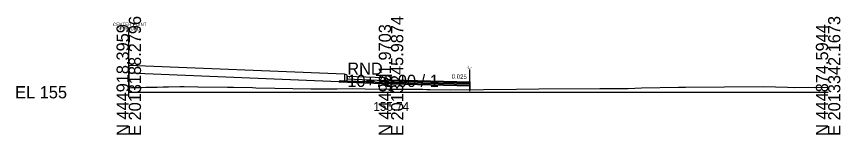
# Model space of a CAD drawing. Extents: x -26 to 163, y -10 to 7518.
# Drawn here: x -25.7 to 162.8, y 1490.3 to 1517.4 of the extents above; entities that cross this region are included whole.
import ezdxf

# ---------------------------------------------------------------- set-up
doc = ezdxf.new("R2010")
doc.units = 0
for name, color, linetype in [('Exist Cross Section Cell', 7, 'Continuous'), ('Exist XS Center Line Elevation Label', 7, 'Continuous'), ('Exist XS Ground Line', 7, 'Continuous'), ('Prop CMT Conc Surface', 7, 'Continuous'), ('Prop CMT Concrete Structures', 7, 'Continuous'), ('Prop CMT Pvmt Course 1', 7, 'Continuous'), ('Prop CMT Pvmt Course 1 CG', 7, 'Continuous'), ('Prop CMT Pvmt Course 2', 7, 'Continuous'), ('Prop CMT Pvmt Course 3', 7, 'Continuous'), ('Prop CMT Pvmt Surface', 7, 'Continuous'), ('Prop CMT Shear Line', 7, 'Continuous'), ('Prop CMT Shear Line Text', 7, 'Continuous'), ('Prop CMT Slope Grass', 7, 'Continuous'), ('Prop CMT Subgrade Earthwork', 7, 'Continuous'), ('Prop XS Earthwork Shape', 7, 'Continuous'), ('Prop XS SE Text', 7, 'Continuous')]:
    doc.layers.add(name, color=color, linetype=linetype)

msp = doc.modelspace()

# ---------------------------------------------------------------- linework, layer by layer
at = {"layer": 'Exist Cross Section Cell'}
for p, q in [((60, 1500), (60, 1504.01)), ((0, 1500), (60, 1500)), ((60, 1500), (160, 1500))]:
    msp.add_line(p, q, dxfattribs=at)
at = {"layer": 'Exist XS Ground Line'}
msp.add_lwpolyline([(0, 1501.05), (0.62, 1501.07), (1.28, 1501.08), (2.96, 1501.11), (3.88, 1501.13), (4.24, 1501.14), (6.47, 1501.19), (7.87, 1501.22), (9.06, 1501.24), (11.68, 1501.3), (12.09, 1501.31), (12.69, 1501.31), (15.79, 1501.24), (22.57, 1501.13), (23.98, 1501.14), (28.29, 1501.07), (29.1, 1501.05), (33.4, 1500.92), (41.68, 1500.81), (46.12, 1500.76), (47.66, 1500.75), (51.09, 1500.83), (54.12, 1500.79), (60, 1500.74), (67.25, 1500.68), (68.23, 1500.67), (68.95, 1500.66), (73.61, 1500.59), (88.71, 1500.68), (93.79, 1500.76), (107.77, 1500.83), (114.24, 1500.87), (117.29, 1501), (125.76, 1501.18), (126.54, 1501.19), (127.38, 1501.2), (145.24, 1501.34), (150.72, 1501.14), (152.39, 1501.11), (157.08, 1501.14), (160, 1501.1)], dxfattribs=at)
at = {"layer": 'Prop CMT Conc Surface'}
for points in [[(50, 1503.82), (49.96, 1503.92), (49.85, 1503.96), (49.34, 1504.15)], [(50, 1503.65), (50, 1503.82)], [(60, 1502.85), (59.25, 1502.87), (59.25, 1503.04), (58.5, 1503.29)]]:
    msp.add_lwpolyline(points, dxfattribs=at)
at = {"layer": 'Prop CMT Concrete Structures'}
for points in [[(50, 1503.82), (49.96, 1503.92), (49.85, 1503.96), (49.34, 1504.15)], [(49.34, 1504.15), (49.34, 1502.65)], [(49.34, 1502.65), (50, 1502.65)], [(50, 1503.65), (50, 1503.82)], [(50, 1502.65), (50, 1503.65)], [(50, 1503.65), (50, 1503.07)], [(58.5, 1503.29), (50, 1503.63)], [(50, 1503.05), (58.5, 1502.71)], [(60, 1502.85), (59.25, 1502.87), (59.25, 1503.04), (58.5, 1503.29)], [(58.5, 1503.29), (58.5, 1502.31)], [(58.5, 1502.71), (58.5, 1503.29)], [(60, 1502.27), (60, 1502.85)], [(58.5, 1502.31), (60, 1502.27)]]:
    msp.add_lwpolyline(points, dxfattribs=at)
at = {"layer": 'Prop CMT Pvmt Course 1'}
for points in [[(60, 1502.85), (78, 1502.4)], [(60, 1502.6), (60, 1502.85)], [(78, 1502.15), (60, 1502.6)], [(78, 1502.4), (78, 1502.15)]]:
    msp.add_lwpolyline(points, dxfattribs=at)
msp.add_lwpolyline([(60, 1502.6), (60, 1502.73), (60, 1502.73), (60, 1502.6)], close=True, dxfattribs=at)
at = {"layer": 'Prop CMT Pvmt Course 1 CG'}
for points in [[(60, 1501.94), (60, 1502.27)], [(78, 1501.49), (78, 1501.82)]]:
    msp.add_lwpolyline(points, dxfattribs=at)
at = {"layer": 'Prop CMT Pvmt Course 2'}
for points in [[(60, 1502.27), (60, 1502.6)], [(60, 1502.6), (78, 1502.15)], [(78, 1501.82), (60, 1502.27)], [(78, 1502.15), (78, 1501.82)]]:
    msp.add_lwpolyline(points, dxfattribs=at)
at = {"layer": 'Prop CMT Pvmt Course 3'}
for points in [[(50, 1502.65), (58.5, 1502.31)], [(60, 1502.27), (78, 1501.82)], [(60, 1501.94), (60, 1502.27)], [(78, 1501.49), (60, 1501.94)], [(78, 1501.82), (78, 1501.49)]]:
    msp.add_lwpolyline(points, dxfattribs=at)
at = {"layer": 'Prop CMT Pvmt Surface'}
msp.add_lwpolyline([(60, 1502.85), (78, 1502.4)], dxfattribs=at)
at = {"layer": 'Prop CMT Shear Line'}
for p, q in [((0, 1498.92), (0, 1513.92)), ((78, 1500.23), (78, 1505.24))]:
    msp.add_line(p, q, dxfattribs=at)
at = {"layer": 'Prop CMT Slope Grass'}
for p, q in [((49.34, 1504.13), (0, 1506.11)), ((48.06, 1502.42), (0, 1504.34))]:
    msp.add_line(p, q, dxfattribs=at)
at = {"layer": 'Prop CMT Subgrade Earthwork'}
for p, q in [((0, 1506.11), (0, 1501.05)), ((48.34, 1502.69), (48.06, 1502.42)), ((78, 1502.4), (78, 1501.49)), ((78, 1501.49), (78, 1500.62))]:
    msp.add_line(p, q, dxfattribs=at)
for points in [[(48.34, 1502.69), (49.34, 1502.65)], [(48.06, 1502.42), (60, 1501.94)], [(60, 1501.94), (78, 1501.49)]]:
    msp.add_lwpolyline(points, dxfattribs=at)
at = {"layer": 'Prop XS Earthwork Shape'}
msp.add_lwpolyline([(46.12, 1500.76), (47.66, 1500.75), (51.09, 1500.83), (54.12, 1500.79), (60, 1500.74), (67.25, 1500.68), (68.23, 1500.67), (68.95, 1500.66), (73.61, 1500.59), (78, 1500.62), (78, 1501.49), (60, 1501.94), (48.06, 1502.42), (0, 1504.34), (0, 1501.05), (0.62, 1501.07), (1.28, 1501.08), (2.96, 1501.11), (3.88, 1501.13), (4.24, 1501.14), (6.47, 1501.19), (7.87, 1501.22), (9.06, 1501.24), (11.68, 1501.3), (12.09, 1501.31), (12.69, 1501.31), (15.79, 1501.24), (22.57, 1501.13), (23.98, 1501.14), (28.29, 1501.07), (29.1, 1501.05), (33.4, 1500.92), (41.68, 1500.81)], close=True, dxfattribs=at)

# ---------------------------------------------------------------- texts
at = {"layer": 'Exist Cross Section Cell'}
for s, p in [('E 2013188.2796', (2.8, 1490)), ('E 2013245.9874', (62.8, 1490)), ('E 2013342.1673', (162.8, 1490)), ('N 444918.3959', (0, 1490)), ('N 444901.9703', (60, 1490)), ('N 444874.5944', (160, 1490))]:
    msp.add_text(s, height=2.8, rotation=90, dxfattribs=at).set_placement(p)
for s, p in [('RND', (50, 1504.01)), ('10+75.00 / 1', (50, 1501.21)), ('EL 155', (-26, 1498.6))]:
    msp.add_text(s, height=2.8, dxfattribs=at).set_placement(p)
at = {"layer": 'Exist XS Center Line Elevation Label'}
msp.add_text('155.74', height=2, dxfattribs=at).set_placement((55.96, 1495.74))
at = {"layer": 'Prop CMT Shear Line Text'}
for s, p in [('CENTER POINT', (-3.64, 1515.17)), ('OF ROUND', (-2.88, 1514.19)), ('-L-', (77.27, 1505.36))]:
    msp.add_text(s, height=0.75, dxfattribs=at).set_placement(p)
at = {"layer": 'Prop XS SE Text'}
msp.add_text('0.025', height=1, rotation=358.5613, dxfattribs=at).set_placement((73.87, 1503.13))

doc.saveas('drawing.dxf')
